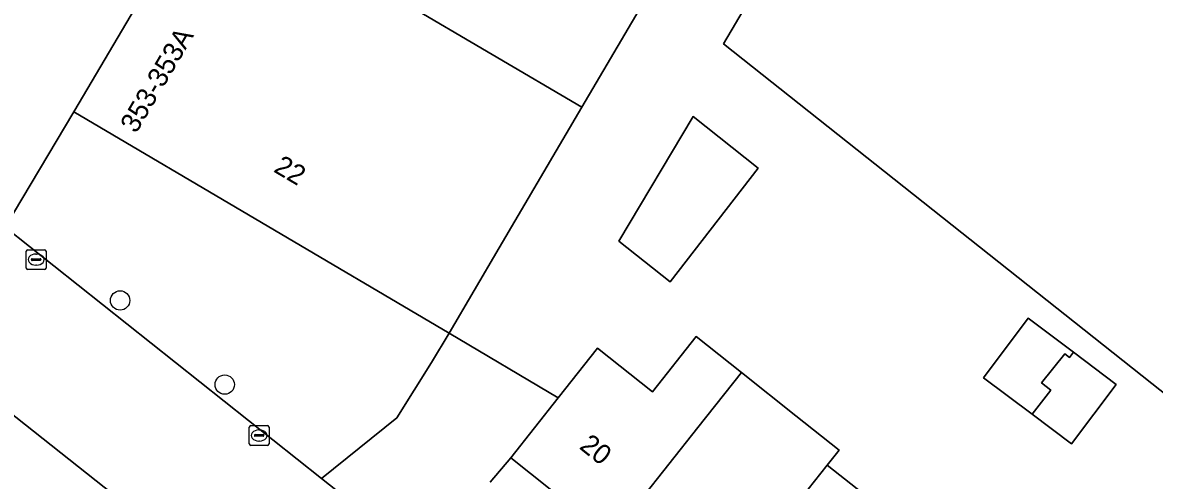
# Model space of a CAD drawing. Extents: x 159217 to 160349, y 381246 to 382172.
# Drawn here: x 160138.1 to 160195.3, y 382022.9 to 382046 of the extents above; entities that cross this region are included whole.
import ezdxf

# ---------------------------------------------------------------- set-up
doc = ezdxf.new("R2010")
doc.units = 0
for name, color, linetype in [('IMGEO_Boom', 7, 'Continuous'), ('IMGEO_Erf', 7, 'Continuous'), ('IMGEO_Kolk', 7, 'Continuous'), ('IMGEO_Pand', 7, 'Continuous'), ('IMGEO_Pand_nummerreeks', 7, 'Continuous'), ('IMGEO_Rijbaan_lokaal_open', 7, 'Continuous'), ('IMGEO_Voetpad_open', 7, 'Continuous')]:
    doc.layers.add(name, color=color, linetype=linetype)

msp = doc.modelspace()

# ---------------------------------------------------------------- linework, layer by layer
at = {"layer": 'IMGEO_Boom'}
for centre in [(160143.026, 382031.994), (160148.316, 382027.742)]:
    msp.add_circle(centre, 0.489, dxfattribs=at)
at = {"layer": 'IMGEO_Erf'}
for points in [[(160175.635, 382057.474), (160166.38, 382041.758), (160162.197, 382034.654), (160159.659, 382030.345), (160165.183, 382027.072), (160167.174, 382029.585), (160169.951, 382027.385), (160172.155, 382030.167), (160174.443, 382028.355), (160177.204, 382026.169), (160179.392, 382024.435), (160178.788, 382023.674), (160181.806, 382021.284)], [(160198.054, 382025.542), (160173.539, 382044.963), (160179.55, 382055.171)], [(160167.842, 382020.023), (160162.777, 382024.035), (160161.732, 382022.812)]]:
    msp.add_lwpolyline(points, dxfattribs=at)
for points in [[(160170.842, 382032.934), (160168.239, 382034.996), (160172.003, 382041.283), (160175.286, 382038.68)], [(160191.141, 382024.742), (160189.14, 382026.246), (160186.688, 382028.089), (160188.95, 382031.1), (160191.238, 382029.381), (160193.403, 382027.755)]]:
    msp.add_lwpolyline(points, close=True, dxfattribs=at)
at = {"layer": 'IMGEO_Kolk'}
for p, q in [((160138.354, 382034.559), (160139.206, 382034.559)), ((160138.279, 382033.633), (160138.279, 382034.485)), ((160138.538, 382034.053), (160138.538, 382034.065)), ((160138.976, 382034.016), (160138.578, 382034.016)), ((160138.581, 382034.102), (160138.979, 382034.102)), ((160138.767, 382034.339), (160138.792, 382034.339)), ((160139.022, 382034.065), (160139.022, 382034.053)), ((160139.28, 382034.485), (160139.28, 382033.633)), ((160139.206, 382033.559), (160138.354, 382033.559)), ((160138.79, 382033.779), (160138.765, 382033.779)), ((160149.556, 382024.746), (160149.556, 382025.598)), ((160149.631, 382025.672), (160150.483, 382025.672)), ((160150.044, 382025.452), (160150.069, 382025.452)), ((160150.557, 382025.598), (160150.557, 382024.746)), ((160149.815, 382025.166), (160149.815, 382025.178)), ((160150.253, 382025.129), (160149.855, 382025.129)), ((160149.858, 382025.215), (160150.256, 382025.215)), ((160150.067, 382024.892), (160150.042, 382024.892)), ((160150.299, 382025.178), (160150.299, 382025.166)), ((160150.483, 382024.672), (160149.631, 382024.672))]:
    msp.add_line(p, q, dxfattribs=at)
for points in [[(160138.354, 382034.559), (160139.206, 382034.559)], [(160138.279, 382033.633), (160138.279, 382034.485)], [(160139.28, 382034.485), (160139.28, 382033.633)], [(160139.206, 382033.559), (160138.354, 382033.559)], [(160149.556, 382024.746), (160149.556, 382025.598)], [(160149.631, 382025.672), (160150.483, 382025.672)], [(160150.557, 382025.598), (160150.557, 382024.746)], [(160150.483, 382024.672), (160149.631, 382024.672)]]:
    msp.add_lwpolyline(points, dxfattribs=at)
for centre, radius, start, end in [((160138.356, 382034.483), 0.0765, 91.552, 178.448), ((160138.356, 382034.483), 0.0765, 91.552, 178.448), ((160139.204, 382034.483), 0.0765, 1.552, 88.448), ((160139.204, 382034.483), 0.0765, 1.552, 88.448), ((160138.578, 382034.062), 0.0403, 85.8775, 175.7526), ((160138.575, 382034.052), 0.0366, 178.938, 274.7102), ((160138.979, 382034.059), 0.043, 264.8664, 352.4533), ((160138.983, 382034.064), 0.0386, 1.7309, 96.639), ((160138.356, 382033.635), 0.0765, 181.552, 268.448), ((160138.356, 382033.635), 0.0765, 181.552, 268.448), ((160139.204, 382033.635), 0.0765, 271.552, 358.448), ((160139.204, 382033.635), 0.0765, 271.552, 358.448), ((160149.633, 382025.596), 0.0765, 91.552, 178.448), ((160149.633, 382025.596), 0.0765, 91.552, 178.448), ((160150.481, 382025.596), 0.0765, 1.552, 88.448), ((160150.481, 382025.596), 0.0765, 1.552, 88.448), ((160149.855, 382025.175), 0.0403, 85.8775, 175.7526), ((160149.852, 382025.165), 0.0366, 178.938, 274.7102), ((160150.256, 382025.172), 0.043, 264.8664, 352.4533), ((160150.26, 382025.177), 0.0386, 1.7309, 96.639), ((160149.633, 382024.748), 0.0765, 181.552, 268.448), ((160149.633, 382024.748), 0.0765, 181.552, 268.448), ((160150.481, 382024.748), 0.0765, 271.552, 358.448), ((160150.481, 382024.748), 0.0765, 271.552, 358.448)]:
    msp.add_arc(centre, radius, start, end, dxfattribs=at)
for centre, major_axis, ratio, start_param, end_param in [((160138.766, 382034.059), (-0.387, 0.002), 0.722429, 4.712389, 7.853982), ((160138.791, 382034.059), (-0.39, 0.002), 0.717154, 1.570796, 4.712389), ((160150.043, 382025.172), (-0.387, 0.002), 0.722429, 4.712389, 7.853982), ((160150.068, 382025.172), (-0.39, 0.002), 0.717154, 1.570796, 4.712389)]:
    msp.add_ellipse(centre, major_axis=major_axis, ratio=ratio, start_param=start_param, end_param=end_param, dxfattribs=at)
at = {"layer": 'IMGEO_Pand'}
msp.add_lwpolyline([(160198.078, 382086.661), (160185.01, 382064.558), (160182.923, 382060.898), (160179.55, 382055.171), (160173.539, 382044.963), (160198.054, 382025.542)], dxfattribs=at)
for points in [[(160160.817, 382073.722), (160159.458, 382071.414), (160158.659, 382071.884), (160154.787, 382065.308), (160155.581, 382064.841), (160153.126, 382060.673), (160152.3, 382061.16), (160148.43, 382054.589), (160149.236, 382054.114), (160148.242, 382052.427), (160166.38, 382041.758), (160175.635, 382057.474), (160178.908, 382063.032)], [(160148.242, 382052.427), (160147.249, 382050.74), (160145.773, 382050.151), (160140.689, 382041.517), (160159.659, 382030.345), (160162.197, 382034.654), (160166.38, 382041.758)], [(160168.239, 382034.996), (160170.842, 382032.934), (160175.286, 382038.68), (160172.003, 382041.283)], [(160190.794, 382029.304), (160191.03, 382029.118), (160191.238, 382029.381), (160188.95, 382031.1), (160186.688, 382028.089), (160189.14, 382026.246), (160190.097, 382027.455), (160189.626, 382027.828)], [(160174.443, 382028.355), (160172.155, 382030.167), (160169.951, 382027.385), (160167.174, 382029.585), (160165.183, 382027.072), (160162.777, 382024.035), (160167.842, 382020.023), (160172.238, 382025.573)], [(160193.403, 382027.755), (160191.238, 382029.381), (160191.03, 382029.118), (160190.794, 382029.304), (160189.626, 382027.828), (160190.097, 382027.455), (160189.14, 382026.246), (160191.141, 382024.742)], [(160178.788, 382023.674), (160179.392, 382024.435), (160177.204, 382026.169), (160174.443, 382028.355), (160172.238, 382025.573), (160167.842, 382020.023), (160172.79, 382016.103), (160177.187, 382021.653)], [(160182.135, 382017.733), (160180.205, 382019.262), (160181.806, 382021.284), (160178.788, 382023.674), (160177.187, 382021.653), (160172.79, 382016.103), (160177.738, 382012.183)]]:
    msp.add_lwpolyline(points, close=True, dxfattribs=at)
at = {"layer": 'IMGEO_Rijbaan_lokaal_open'}
for points in [[(160193.666, 381990.913), (160184.067, 381998.574), (160166.634, 382012.378), (160159.669, 382017.89), (160153.216, 382022.998), (160137.206, 382035.701), (160135.457, 382037.171)], [(160132.773, 382030.024), (160147.666, 382018.247), (160148.418, 382017.652), (160152.766, 382014.214), (160170.741, 382000), (160222.676, 381958.931)]]:
    msp.add_lwpolyline(points, dxfattribs=at)
at = {"layer": 'IMGEO_Voetpad_open'}
for points in [[(160135.457, 382037.171), (160137.206, 382035.701), (160140.689, 382041.517), (160145.773, 382050.151), (160147.249, 382050.74), (160148.242, 382052.427), (160149.236, 382054.114), (160148.43, 382054.589), (160152.3, 382061.16), (160153.126, 382060.673), (160155.581, 382064.841), (160154.787, 382065.308), (160158.659, 382071.884)], [(160127.222, 382030.546), (160130.774, 382027.732), (160146.492, 382015.319), (160148.418, 382017.652), (160147.666, 382018.247), (160132.773, 382030.024)], [(160165.183, 382027.072), (160159.659, 382030.345), (160158.778, 382028.852), (160157.025, 382026.062), (160153.216, 382022.998), (160159.669, 382017.89), (160161.552, 382020.389)], [(160161.732, 382022.812), (160162.777, 382024.035), (160165.183, 382027.072)]]:
    msp.add_lwpolyline(points, dxfattribs=at)
msp.add_lwpolyline([(160140.689, 382041.517), (160137.206, 382035.701), (160153.216, 382022.998), (160157.025, 382026.062), (160158.778, 382028.852), (160159.659, 382030.345)], close=True, dxfattribs=at)

# ---------------------------------------------------------------- texts
at = {"layer": 'IMGEO_Pand_nummerreeks'}
for s, rotation, p in [('353-353A', 59.5089, (160143.834, 382040.394)), ('22', 329.5049, (160150.738, 382038.523)), ('20', 321.6118, (160166.199, 382024.539))]:
    msp.add_text(s, height=1, rotation=rotation, dxfattribs=at).set_placement(p)

doc.saveas('drawing.dxf')
